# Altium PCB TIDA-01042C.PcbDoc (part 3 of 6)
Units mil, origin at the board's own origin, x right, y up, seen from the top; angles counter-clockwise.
Board outline 8300 x 7100 mil, 8 copper layers (Top Layer, Signal Layer 1, Signal Layer 2, Signal Layer 3, Signal Layer 4, Signal Layer 5, Signal Layer 6, Bottom Layer), stack 59.2 mil thick; 551 components, 303 nets, 1611 pads, 2322 vias.
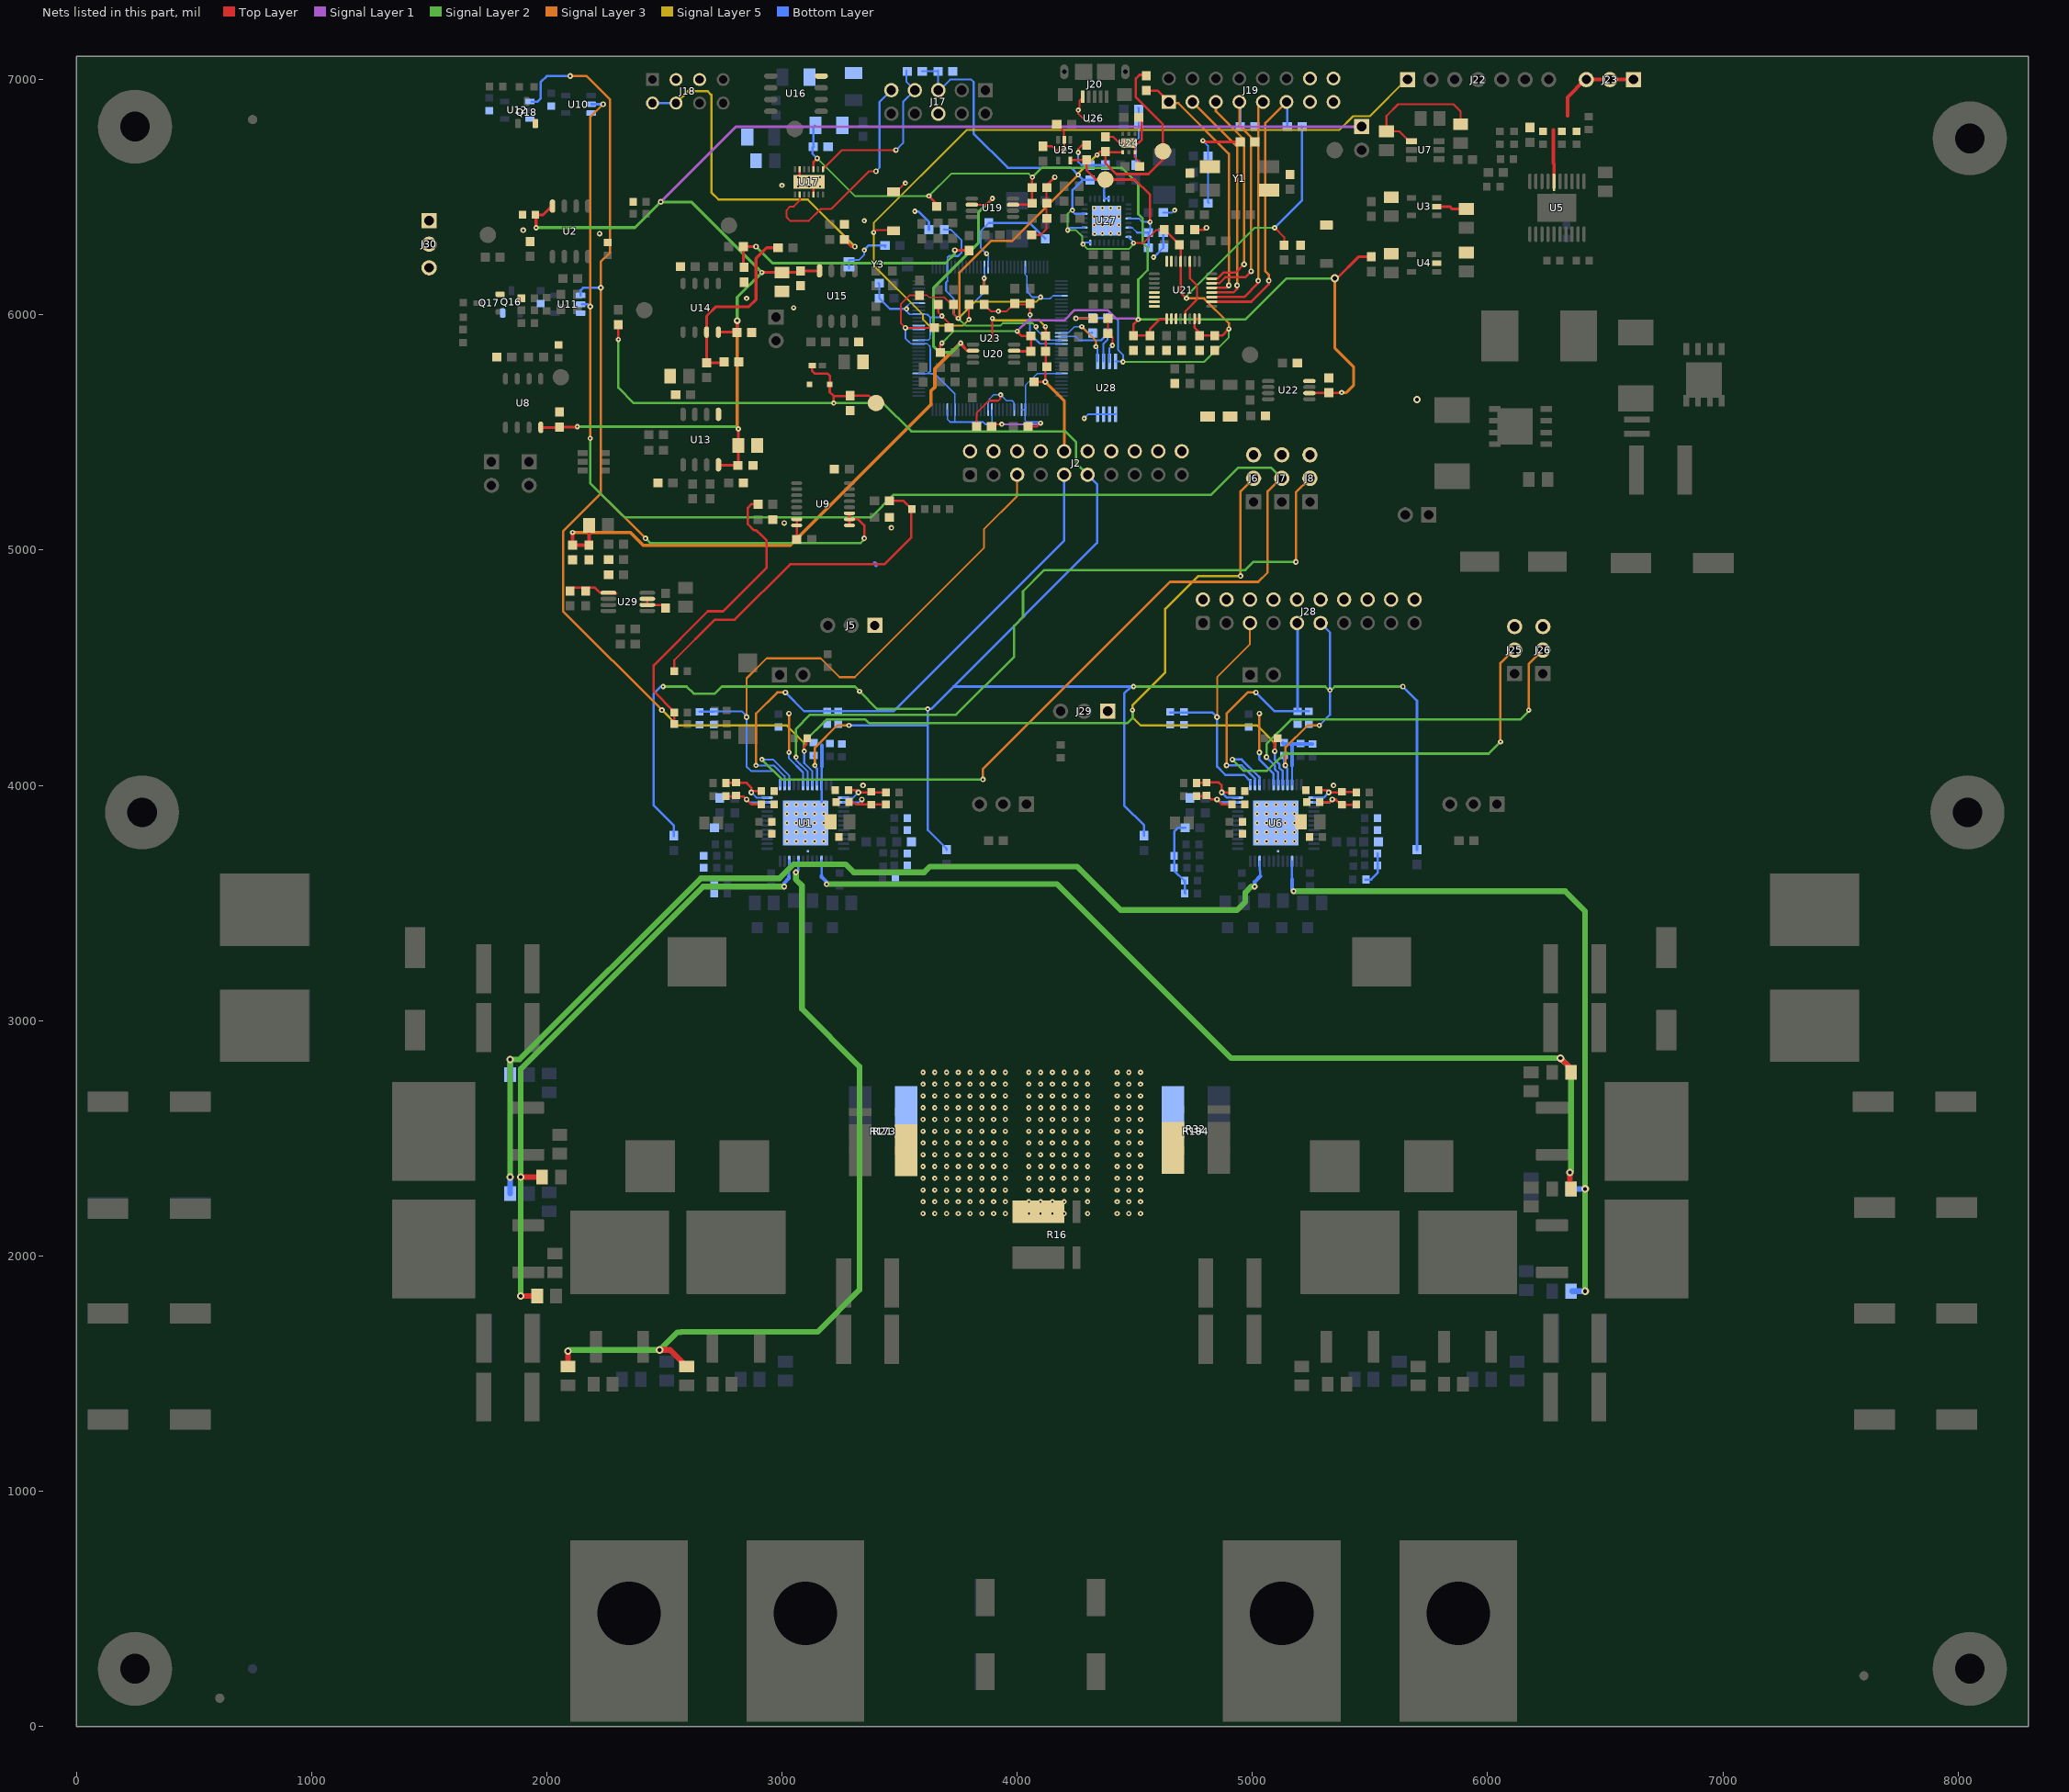
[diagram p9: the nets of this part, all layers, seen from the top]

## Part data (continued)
R113 R115 R128 R130: library part CMP-0022448-4, "RES, 49.9, 1%, 0.1 W, AEC-Q200 Grade 0, 0603", Manufacturer=Vishay-Dale, PartNumber=CRCW060349R9FKEA, Power_W=100mW, Supplier Part Number 1=541-49.9HCT-ND, TempCo="100 ppm/C", Tolerance_%=1%, Value2=0.1W, Value_Code=49R9, ValueDisplayed=49.9
R116 R121 R122 R123 R131: library part CMP-0021990-4, "RES, 100 k, 1%, 0.1 W, AEC-Q200 Grade 0, 0603", Manufacturer=Vishay-Dale, PartNumber=CRCW0603100KFKEA, Power_W=100mW, Supplier Part Number 1=541-100KHCT-ND, TempCo="100 ppm/C", Tolerance_%=1%, Value2=0.1W, Value_Code=100k
R118 R119 R125 R127: library part CMP-0021991-4, "RES, 100, 1%, 0.1 W, AEC-Q200 Grade 0, 0603", Manufacturer=Vishay-Dale, PartNumber=CRCW0603100RFKEA, Power_W=100mW, Supplier Part Number 1=541-100HCT-ND, TempCo="100 ppm/C", Tolerance_%=1%, Value2=0.1W, Value_Code=100R, ValueDisplayed=100
R126 R129: library part CMP-0023081-3, "RES, 3.30 k, 1%, 0.1 W, 0603", Manufacturer="Yageo America", Power_W=100mW, Supplier Part Number 1=311-3.30KHRCT-ND, TempCo="200 ppm/C", Tolerance_%=1%, Value2=0.1W, Value_Code=3k30, ValueDisplayed=3.30k
R134: library part CMP-0022170-4, "RES, 1.00, 1%, 0.1 W, AEC-Q200 Grade 0, 0603", Manufacturer=Vishay-Dale, PartNumber=CRCW06031R00FKEA, Power_W=100mW, Supplier Part Number 1=52K8059, TempCo="100 ppm/C", Tolerance_%=1%, Value2=0.1W, Value_Code=1R00, ValueDisplayed=1.00
R137: library part CMP-0022138-4, "RES, 1.00 M, 1%, 0.1 W, AEC-Q200 Grade 0, 0603", Manufacturer=Vishay-Dale, PartNumber=CRCW06031M00FKEA, Power_W=100mW, Supplier Part Number 1=541-1.00MHCT-ND, TempCo="100 ppm/C", Tolerance_%=1%, Value2=0.1W, Value_Code=1M00, ValueDisplayed=1.00M
R138: library part CMP-0022109-5, "RES, 1.00 k, 1%, 0.1 W, AEC-Q200 Grade 0, 0603", Manufacturer=Vishay-Dale, PartNumber=CRCW06031K00FKEA, Power_W=100mW, Supplier Part Number 1=541-1.00KHCT-ND, TempCo="100 ppm/C", Tolerance_%=1%, Value2=0.1W, Value_Code=1k00, ValueDisplayed=1.00k
R140 R150: "RES, 1.00 M, 1%, 0.1 W, 0603", Manufacturer=Vishay-Dale, Power_W=0.1, Supplier Part Number 1=541-1.00MHCT-ND, TempCo="100 ppm/C", Tolerance_%=1, Value1=1%, Value2=0.1W, Value_Code=1M00, ValueDisplayed=1.00M
R141: "RES, 100, 1%, 0.1 W, 0603", Manufacturer=Vishay-Dale, Power_W=0.1, Supplier Part Number 1=541-100HCT-ND, TempCo="100 ppm/C", Tolerance_%=1, Value1=1%, Value2=0.1W, Value_Code=100R, ValueDisplayed=100
R142: "RES, 0, 5%, 0.1 W, 0603", Manufacturer=Vishay-Dale, Power_W=0.1, Supplier Part Number 1=541-0.0GCT-ND, TempCo="200 ppm/C", Tolerance_%=5, Value1=5%, Value2=0.1W, Value_Code=0000, ValueDisplayed=0
R143: "RES, 4.87 k, 1%, 0.1 W, 0603", Manufacturer=Vishay-Dale, Power_W=0.1, Supplier Part Number 1=541-4.87KHCT-ND, TempCo="100 ppm/C", Tolerance_%=1, Value1=1%, Value2=0.1W, Value_Code=4k87, ValueDisplayed=4.87k
R145: "RES, 2.00 k, 1%, 0.1 W, 0603", Manufacturer=Vishay-Dale, Power_W=0.1, Supplier Part Number 1=541-2.00KHCT-ND, TempCo="100 ppm/C", Tolerance_%=1, Value1=1%, Value2=0.1W, Value_Code=2k00, ValueDisplayed=2.00k
R146: "RES, 51, 5%, 0.1 W, 0603", Manufacturer=Vishay-Dale, Power_W=0.1, Supplier Part Number 1=541-51GCT-ND, TempCo="200 ppm/C", Tolerance_%=5, Value1=5%, Value2=0.1W, Value_Code=51R0, ValueDisplayed=51
R149: "RES, 1.00 k, 1%, 0.1 W, 0603", Manufacturer=Vishay-Dale, Power_W=0.1, Supplier Part Number 1=541-1.00KHCT-ND, TempCo="100 ppm/C", Tolerance_%=1, Value1=1%, Value2=0.1W, Value_Code=1k00, ValueDisplayed=1.00k
R153: "RES, 8.06 k, 1%, 0.1 W, 0603", Manufacturer=Vishay-Dale, Power_W=0.1, Supplier Part Number 1=541-8.06KHCT-ND, TempCo="100 ppm/C", Tolerance_%=1, Value1=1%, Value2=0.1W, Value_Code=8k06, ValueDisplayed=8.06k
R162: library part CMP-0025080-3, "RES, 2.00 k, 0.5%, 0.1 W, 0603", Manufacturer="Yageo America", Power_W=100mW, TempCo="50 ppm/C", Tolerance_%=0.5%, Value2=0.1W, Value_Code=2k00, ValueDisplayed=2.00k
R200: library part CMP-0023560-3, "RES, 4.87 k, 0.1%, 0.1 W, 0603", Manufacturer="Susumu Co Ltd", Power_W=100mW, Supplier Part Number 1=RG16P4.87KBCT-ND, TempCo="25 ppm/C", Tolerance_%=0.1%, Value2=0.1W, Value_Code=4k87, ValueDisplayed=4.87k
R201: "RES, 4.70, 0.5%, 0.1 W, 0603", Manufacturer="Yageo America", Power_W=0.1, TempCo="50 ppm/C", Tolerance_%=0.5, Value1=0.5%, Value2=0.1W, Value_Code=4R70, ValueDisplayed=4.70
S1: library part CMP-0002143-3, "Switch, Tactile, SPST-NO, 0.05A, 12V, SMT", CurrentRating_mA=50A, Manufacturer=E-Switch, PartNumber=TL1015AF160QG, Supplier Part Number 1=EG4344CT-ND
S2: "Switch, Tactile, SPST-NO, 0.05A, 12V, SMT", CurrentRating_mA=50, Manufacturer=E-Switch, Supplier Part Number 1=EG4344CT-ND
S3: "Switch"
T1 T2 T3 T4: "Terminal 70A Lug", Manufacturer=Panduit, Supplier Part Number 1=CXS70-14-C-ND
U1 U6: "Dual Channel 48V-12V Bidirectional Current Controller, PHP0048D", Alternate Manufacturer="Texas Instruments", Alternate PartNumber=LM5170QPHPTQ1
U2: library part LM6142AIM, "17MHz Rail-to-Rail Input and Output Op Amp, D0008A", Alternate Manufacturer="Texas Instruments"
U3 U4: "150-mA, 30-V, 1-uA IQ Voltage Regulators with Enable, DBV0005A", Alternate Manufacturer="Texas Instruments", Alternate PartNumber=TPS70950DBVT
U5: "Wide Voltage Range Buck-Boost Controller, 20-pin TSSOP-EP, Pb-Free", Manufacturer="Texas Instruments", PackageTopMarking=NSUZXYTT*LM5118*MH, PowerWise=Y, Supplier Part Number 1=LM5118MH-ND
U7: library part CMP-0072146-1, "Switched Capacitor Voltage Converter, 6-pin SOT-23", Manufacturer="Texas Instruments", PackageTopMarking=S03A*XTT, PowerWise=N
U8 U14: library part CMP-0041267-2, "Low-Noise, High-Precision, JFET-Input Operational Amplifier, 8 to 36 V, -40 to 125 degC, 8-pin SOIC (D8), Green (RoHS & no Sb/Br)", Manufacturer="Texas Instruments"
U9: library part CMP-0076549-1, "TRIPLE 2-CHANNEL ANALOG MULTIPLEXER/DEMULTIPLEXER, PW0016A (TSSOP-16)", Alternate Manufacturer="Texas Instruments"
U10: "Single Inverter Gate, DBV0005A", Alternate Manufacturer="Texas Instruments"
U11: "Single Power Supply 2-Input Positive NAND Gate CMOS Logic Level Shifter, DBV0005A", Alternate Manufacturer="Texas Instruments"
U12: "Single Power Supply 2-Input Positive OR Gate CMOS Logic Level Shifter, DBV0005A", Alternate Manufacturer="Texas Instruments"
U13: library part CMP-0079943-1, "50-uV Offset, 7-nV/vHz Noise, Low-Power, Precision Instrumentation Amplifier, D0008A (SOIC-8)", Alternate Manufacturer="Texas Instruments", Alternate PartNumber=INA828IDR
U15: library part CMP-0079847-1, "36-V Precision, Rail-to-Rail Output, Operational Amplifier, D0008A (SOIC-8)", Alternate Manufacturer="Texas Instruments"
U16: library part CMP-0032617-1, "Low Noise, Very Low Drift, Precision Voltage Reference, -40 to 125 degC, 8-pin SOIC (D), Green (RoHS & no Sb/Br)", Manufacturer="Texas Instruments", PartNumber=REF5050AID, Rating=Catalog, Temp Coeff(Max)(ppm/ degree C)=3
U17: library part CMP-0013342-2, "QUAD 16-BIT, 1LSB INL, BUFFERED, VOLTAGE-OUTPUT DIGITAL-to-ANALOG CONVERTERS, DMD0014A (VSON-14)", Alternate Manufacturer="Texas Instruments", PartNumber=DAC80004IDMD
U19 U20: library part CMP-0074888-1, "Low-Power, High Supply Range, 60-MHz, Fully Differential Amplifier, DGK0008A (VSSOP-8)", Alternate Manufacturer="Texas Instruments", Alternate PartNumber=THS4561IDGKT
U21: library part CMP-0075938-2, "24-Bit, 128kSPS, 4-Ch, Simultaneous Sampling, Delta-Sigma ADC, PBS0032A (TQFP-32)", Alternate Manufacturer="Texas Instruments", Alternate PartNumber=ADS131A04IPBS
U22: library part CMP-0032584-1, "Low Noise, Very Low Drift, Precision Voltage Reference, -40 to 125 degC, 8-pin MSOP(DGK), Green (RoHS & no Sb/Br)", Manufacturer="Texas Instruments", PartNumber=REF5025IDGKR, Rating=Military, Temp Coeff(Max)(ppm/ degree C)=3
U23: library part CMP-0029864-2, "Tiva C Series Microcontroller, 1024 KB Flash, 256 KB SRAM, 12 Bit, 20 Channels, -40 to 85 degC, 128-Pin TQFP (PDT), Green (RoHS & no Sb/Br), Tape and Reel", Manufacturer="Texas Instruments", Temperature Range="-40 to 85 degC"
U24: "1-A Low-Dropout Regulator With Reverse Current Protection, DRV0006A", Alternate Manufacturer="Texas Instruments", Alternate PartNumber=TPS73733DRVT
U25: "Single Output High PSRR LDO, 150 mA, Fixed 1.8 V Output, 2.5 to 6.5 V Input, with Low IQ, 5-pin SC70 (DCK), -40 to 85 degC, Green (RoHS & no Sb/Br)", Alternate Manufacturer="Texas Instruments", Alternate PartNumber=Equivalent, Supplier Part Number 1=296-19646-2-ND
U26: library part CMP-0043122-2, "USB ESD Solution with Power Clamp, 4 Channels, -40 to +85 degC, 6-pin SON (DRY), Green (RoHS & no Sb/Br)", Breakdown Voltage(Min)(V)=6, IO Capacitance(Typ)(pF)=0.8, IO Leakage Current(nA)=10, Manufacturer="Texas Instruments"
U27: "Highly Integrated Full Featured Hi-Speed USB 2.0 ULPI Transceiver, QFN-32", Manufacturer=Microchip, Supplier Part Number 1=USB3320C-EZK-ND
U28: "256K I2C™ CMOS Serial EEPROM, TSSOP-8", Manufacturer=Microchip, Supplier Part Number 1=24AA256-I/ST-ND
U29: "Low Noise Negative Bias Generator, 8-pin Mini SOIC, Pb-Free", Manufacturer="Texas Instruments", PackageTopMarking=ZXTT*F26A, PowerWise=N, Supplier Part Number 1=LM7705MM-ND
Y1: library part CMP-0004606-3, "Crystal, 16.384 MHz, 20 pF, SMD", Frequency_Fixed=16.384MHz, Frequency Stability=+/-50ppm, Manufacturer="CTS Electrocomponents", PartNumber=407F35E016M3840, Supplier Part Number 1=CTX682CT-ND
Y2: "Crystal, 25 MHz, 18 pF, SMD", Frequency="25 MHz", Frequency Stability=±30ppm, Manufacturer="Abracon Corportation", Supplier Part Number 1=535-10645-1-ND
Y3: "CRYSTAL, 32.768KHZ, 7PF, SMD", Frequency=32.768KHZ, Frequency Stability=±20ppm, Manufacturer="Seiko Instruments", Supplier Part Number 1=728-1065-1-ND
Y4: "Crystal, 24 MHz, 18 pF, SMD", Frequency="24 MHz", Frequency Stability=±30ppm, Manufacturer="Abracon Corportation", Supplier Part Number 1=535-10643-1-ND
ZZ1: library part AssemblyNoteLabel, Alternate Manufacturer=-
ZZ2 ZZ3 ZZ4: library part AssemblyNote, Alternate Manufacturer=-

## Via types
v1: diameter 32, hole 16, Top Layer to Bottom Layer, tented both sides, 1077 vias
v2: diameter 22, hole 8, Top Layer to Bottom Layer, tented both sides, 583 vias
v3: diameter 32, hole 16, Top Layer to Bottom Layer, 233 vias
v4: diameter 24, hole 10, Top Layer to Bottom Layer, tented both sides, 153 vias
v5: diameter 24, hole 8, Top Layer to Bottom Layer, 96 vias
v6: diameter 19.68, hole 7.87, Top Layer to Bottom Layer, 70 vias
v7: diameter 24, hole 10, Top Layer to Bottom Layer, 44 vias
v8: diameter 28, hole 8, Top Layer to Bottom Layer, tented top, 24 vias
v9: diameter 22, hole 8, Top Layer to Bottom Layer, 18 vias
v10: diameter 19.68, hole 8, Top Layer to Bottom Layer, 16 vias
v11: diameter 50, hole 28, Top Layer to Bottom Layer, 3 vias
v12: diameter 36, hole 20, Top Layer to Bottom Layer, 2 vias
v13: diameter 26, hole 12, Top Layer to Bottom Layer, 1 vias
v14: diameter 28, hole 12, Top Layer to Bottom Layer, tented both sides, 1 vias
v15: diameter 24, hole 10, Top Layer to Bottom Layer, tented top, 1 vias

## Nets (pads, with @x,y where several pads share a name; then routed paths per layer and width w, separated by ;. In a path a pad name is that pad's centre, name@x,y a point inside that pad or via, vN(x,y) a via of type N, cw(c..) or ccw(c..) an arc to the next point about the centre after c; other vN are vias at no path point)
1.8V: C177.2 C178.2 C183.1 U25.5 U27.28 U27.30 V1.8.1 | length 842.3
  Top Layer w10: U25.5@4225,6660 4226.5,6658.5 C183.1@4295,6658.5 4295,6615 4335,6575 V1.8.1@4375,6575 4500,6575 4565,6510 v2(4565,6395)
  Bottom Layer w6: U27.30@4475,6370 4490,6370 4510,6350 4511.24,6350
  Bottom Layer w8: U27.28@4473.31,6409.84 4517.51,6409.84 4532.35,6395 v2@4560,6395 ; C177.2@4560,6350 4565,6355 v2(4565,6395)
  Bottom Layer w10: 4511.24,6350 C177.2@4558.5,6350 ; C178.2@4555,6285 4558.5,6288.5 C177.2@4558.5,6350 ; C177.2@4560,6350 C177.2@4558.5,6350
-0.2V: C228.1 C229.1 L8.1 U19.6 U20.6 | length 3366.9
  Top Layer w9: U19.6@3807.4,6467.8 3867.8,6467.8 v2(3895,6495)
  Top Layer w12: v2(3760,5880) 3771.95,5868.05 3771.95,5863.97 ; 3770,5865 3787.2,5847.8 U20.6@3812.4,5847.8 U20.6@3809.54,5850.65
  Top Layer w15: C229.1@2105,5025 2108.5,5021.5 C229.1@2110,5021.5 ; v2(2110,5075) C229.1@2110,5021.5 ; C228.1@2180,5021.5 C229.1@2110,5021.5 ; C228.1@2180,5025 L8.1@2180,5105
  Signal Layer 2 w12: v2(3760,5880) 3720,5840 3670,5840 3645,5865 3645,6115 3835,6305 3835,6435 v2(3895,6495)
  Signal Layer 3 w15: v2(2110,5075) 2356.29,5075 2411.29,5020 3035,5020 3633.63,5618.63 3633.63,5676.37 3650,5692.75 3650,5770 v2(3760,5880)
-5V: C97.1 C108.1 C109.1 C112.1 C119.1 C120.1 C189.1 J16.1 U2.4 U8.4 U13.4 U14.4 U15.4 | length 6559.2
  Top Layer w12: v2(1955,6370) 1955,6425 1985,6425 U2.4@2025,6465 ; U8.4@1975,5521.65 2053.35,5521.65 C97.1@2055,5520 ; C97.1@2055,5523.5 v9@2131.5,5523.5 ; U13.4@2730,5362.72 2732.72,5360 C108.1@2813.5,5360 2815,5360 v9(2815,5515) ; U14.4@2730,5926.65 2803.35,5926.65 C112.1@2805,5925 ; C112.1@2808.5,5925 v14@2808.5,5973.5 ; v2(2915,6180) C120.1@3000,6180 3080,6180 3087.28,6187.28 U15.4@3160,6187.28
  Signal Layer 1 w12: v4(2485,6480) 2805,6800 J16.1@5465,6800
  Signal Layer 2 w12: v2(1955,6370) 1955.87,6370.87 2375.87,6370.87 v4(2485,6480) 2615,6480 v2(2915,6180) 2810,6075 v14(2810,5975) ; v9(2130,5525) 2805,5525 v9(2815,5515)
  Signal Layer 3 w12: v14(2810,5975) 2810,5515 v9@2815,5510
ADC_SPI_CS: J19.5 U21.23 | length 902.8
  Top Layer w10: U21.23@4827.05,6154.21 4827.95,6155.12 4852.54,6155.12 4877.42,6180 4930,6180 v7(4965,6215)
  Signal Layer 3 w10: J19.5@4845,6905 4845,6865 4965,6745 v7(4965,6215)
ADC_SPI_DONE: J19.11 R123.1 U21.18 | length 1198.6
  Top Layer w10: U21.18@4827.05,6055.79 4995.79,6055.79 5070,6130 v7(5070,6145)
  Signal Layer 3 w10: v7(5070,6145) 5070,6170 5055,6185 5055,6815 J19.11@5145,6905
  Bottom Layer w10: J19.11@5145,6905 5148.5,6901.5 R123.1@5148.5,6800
ADC_SPI_DRDY: J19.9 U21.19 | length 1000.9
  Top Layer w10: U21.19@4827.05,6075.47 4965.47,6075.47 5025,6135 v7(5025,6145)
  Signal Layer 3 w10: v7(5025,6145) 5025,6165 5025,6885 J19.9@5045,6905
ADC_SPI_MISO: J19.1 R122.1 U21.21 | length 1098.4
  Top Layer w10: R122.1@4550,6953.5 4596.5,6953.5 J19.1@4645,6905 J19.1@4646.5,6903.5 ; U21.21@4827.05,6114.84 4889.84,6114.84 v7(4900,6125)
  Signal Layer 3 w10: J19.1@4645,6900 4685,6900 4900,6685 v7(4900,6125)
ADC_SPI_MOSI: J19.3 U21.20 | length 987.8
  Top Layer w10: U21.20@4827.05,6095.16 4920.16,6095.16 4935,6110 v7(4935,6125)
  Signal Layer 3 w10: J19.3@4745,6905 4935,6715 v7(4935,6125)
ADC_SPI_SCLK: J19.7 R138.2 U21.22 | length 1043.1
  Top Layer w10: U21.22@4827.05,6134.53 4859.53,6134.53 4885,6160 4970,6160 v7(4995,6185)
  Signal Layer 3 w10: J19.7@4945,6910 J19.7@4945,6905 4945,6805 4995,6755 v7(4995,6185)
  Bottom Layer w10: J19.7@4940,6905 4948.5,6896.5 R138.2@4948.5,6800
AGND: C1.2 C2.1 C3.1 C5.2 C6.2 C8.2 C9.1 C11.2 C13.2 C14.2 C16.2 C17.2 C19.1 C31.2 C33.2 C34.2 C35.2 C36.2 C37.2 C44.2 C45.2 C72.2 C73.2 C74.2 C75.2 C76.2 C78.2 C82.2 C83.2 C84.2 C90.2 C91.1 C93.2 C94.1 C96.2 C97.2 C98.2 C99.1 C100.2 C104.2 C105.2 C106.2 C107.2 C108.2 C109.2 C110.2 C111.2 C112.2 C113.1 C116.2 C117.2 C118.1 C119.2 C120.2 C121.1 C122.2 C123.2 C124.2 C125.2 C126.2 C127.2 C128.2 C131.2 C132.2 C133.2 C134.2 C135.2 C136.2 C137.2 C138.2 C139.2 C140.2 C141.2 C145.1 C146.1 C149.1 C152.2 C153.2 C155.2 C156.2 C157.2 C158.2 C159.2 C160.2 C161.2 C189.2 C190.2 C191.2 C194.2 C196.2 C197.2 C199.2 C200.2 C202.2 C203.2 C204.2 C205.2 C218.2 C223.2 C224.2 C225.2 C226.2 C227.2 C228.2 C229.2 D5.2 J2.2 J2.4 J2.6 J2.8 J2.10 J2.12 J2.14 J2.16 J2.18 J2.20 J5.1 J6.3 J7.3 J8.3 J17.6 J18.3 J18.5 J19.13 J19.14 J19.15 J19.16 J23.1 J23.2 J23.3 J25.3 J26.3 J28.2 J28.4 J28.6 J28.8 J28.10 J28.12 J28.14 J28.16 J28.18 J28.20 J29.1 J30.1 J30.2 J30.3 NT1.1 NT2.1 NT3.1 Q16.2 Q17.2 Q18.2 R2.2 R3.2 R6.1 R7.2 R9.2 R11.1 R13.1 R15.1 R17.1 R18.1 R19.1 R20.1 R23.2 R46.1 R49.1 R67.1 R78.1 R86.2 R87.1 R89.2 R92.1 R112.1 R126.1 R138.1 R147.2 R148.1 R156.1 R158.1 R167.1 R169.1 R170.1 R171.1 R172.1 S1.2 U1.42 U1.46 U1.49 U3.2 U4.2 U5.6 U6.42 U6.46 U6.49 U7.1 U9.7 U9.8 U10.3 U11.3 U12.3 U13.5 U16.4 U17.6 U17.12 U17.15 U21.5 U21.6 U21.7 U21.8 U21.10 U21.11 U21.13 U21.27 U21.31 U21.32 U22.4 U29.2 U29.3 U29.5 Y1.2 Y1.4 | length 5161.6
  Top Layer w8: 3895,5895 v2(3895,5985)
  Top Layer w9: R112.1@4061.5,6340 4100,6340 4125,6365 C134.2@4125,6540 ; C132.2@4120,5770 C132.2@4130,5780 ; v2(4120,5950) 4121.5,5948.5 C136.2@4121.5,5910 C135.2@4121.5,5845 ; C132.2@4121.5,5788.5 C132.2@4125,5785 ; C134.2@4126.5,6540 4126.5,6551.5 v4(4160,6585) ; U21.13@4715,5985 4715,6015 4765,6065 4765,6125 4734.53,6155.47 U21.27@4734.53,6227.05 ; U21.27@4733.12,6228.12 U21.27@4735,6230 ; C156.2@4755,6361.5 4796.5,6361.5 v4(4805,6370) ; U7.1@5676.93,6737.4 5667.6,6737.4 5625,6780 C78.2@5570,6780 5570,6845 5620,6895 5855,6895 5885,6865 C76.2@5885,6810
  Top Layer w9.8: C225.2@2095,4840 2205,4840 2226.61,4818.39 U29.5@2262.32,4818.39 2266.28,4814.43 2295.89,4814.43 ; U29.2@2427.68,4767.2 2487.8,4767.2 C223.2@2510,4745 ; U29.2@2427.68,4767.68 U29.3@2427.68,4792.8 ; U9.7@3062.8,5131.02 U9.8@3062.8,5105.43 3062.8,5042.2 R67.1@3065,5040
  Top Layer w10: U17.15@3065,6585 3075.63,6595.63 U17.6@3075.63,6619.13 ; U17.12@3134.69,6510.87 3134.69,6544.68 U17.15@3135,6545 ; R126.1@4071.5,5715 v4(4120,5715) C132.2@4120,5770 ; C132.2@4121.5,5788.5 C135.2@4121.5,5845
  Top Layer w13: U3.2@5777.24,6460 U3.2@5784.13,6460 5840,6460 5850,6450 C34.2@5910,6450 ; 6280,6645 6282.2,6642.8 U5.6@6282.2,6567.2
  Top Layer w15: 6340,6845 6340,6925 6415,7000 J23.3@6420,7000 J23.2@6520,7000 J23.1@6620,7000
  Top Layer w16: v6(3178.74,3840) C6.2@3214.57,3840 ; 6280,6645 6280,6785
  Signal Layer 3 w10: v2(3030,4140) v4(3030,4305) ; v4(5030,4140) v4(5030,4305)
  Signal Layer 3 w12: v4(4120,5715) 4200,5635 J2.10@4200,5420 J2.10@4200,5400
  Signal Layer 5 w9: v2(3895,5985) 3903.37,5976.63 4093.37,5976.63 v2(4120,5950)
  Bottom Layer w8: v2@3030,4137.7 3030,4115 3090.16,4054.84 U1.42@3090.16,3998.46
  Bottom Layer w9: U6.46@5168.9,4002.4 5168.9,4083.9
  Bottom Layer w9.8: U1.49@3168.9,3928.58 3168.9,3998.46 3168.9,4080 ; R170.1@4710,3595 4667.44,3637.56 C19.1@4667.44,3700 4667.44,3802.44 4685,3820 R167.1@4713.5,3820 R167.1@4715,3820 ; R170.1@4712.44,3595 4712.44,3542.56 C203.2@4715,3540 ; v4(5030,4140) 5030,4110 5079.68,4060.32 5079.68,4060.01 5090.16,4049.53 U6.42@5090.16,4002.4 ; C197.2@5480,3600 C197.2@5482.56,3600 5505.12,3600 5532.56,3627.44 R172.1@5532.56,3710
  Bottom Layer w16: 3170,4080 3170,4088.9 ; 3170,4092.8 3170,4170 ; 3395,4945 3400,4940 3400,4935 ; C196.2@5130,4180 5134.11,4175.89 5168.9,4175.89 ; 5168.9,4083.9 5168.9,4175.89 ; 5168.9,4178.9 5168.9,4175.89 ; R148.1@5255,4175.89 5168.9,4175.89
  other v1: 5700,5640
  other v4: 3345,4000 5345,4000 3465,5095 3010,5115 2225,6345 1900,6360
  other v6: 3021.26,3761.26 3060.63,3761.26 3100,3761.26 3139.37,3761.26 3178.74,3761.26 5021.26,3761.26 5060.63,3761.26 5100,3761.26 5139.37,3761.26 5178.74,3761.26 3021.26,3800.63 3060.63,3800.63 3100,3800.63 3139.37,3800.63 3178.74,3800.63 5021.26,3800.63 5060.63,3800.63 5100,3800.63 5139.37,3800.63 5178.74,3800.63 3021.26,3840 3060.63,3840 3100,3840 3139.37,3840 5021.26,3840 5060.63,3840 5100,3840 5139.37,3840 5178.74,3840 3021.26,3879.37 3060.63,3879.37 3100,3879.37 3139.37,3879.37 3178.74,3879.37 5021.26,3879.37 5060.63,3879.37 5100,3879.37 5139.37,3879.37 5178.74,3879.37 3021.26,3918.74 3060.63,3918.74 3100,3918.74 3139.37,3918.74 3178.74,3918.74 5021.26,3918.74 5060.63,3918.74 5100,3918.74 5139.37,3918.74 5178.74,3918.74 3067.76,6545.32 3115,6545.32 3162.24,6545.32 3067.76,6584.68 3115,6584.68 3162.24,6584.68
  other v9: 3050,6030 2850,6070 3350,6400 3000,6550
AVDD: C126.1 C127.1 C133.1 C134.1 C135.1 C136.1 C137.1 C138.1 C160.1 R116.2 R131.2 R165.2 U17.3 U19.3 U20.3 U21.9 U22.2 | length 5801.1
  Top Layer w10: U17.3@3134.69,6619.13 3134.69,6649.68 v7(3150,6665) ; v2(3625,6505) 3658.5,6471.5 R116.2@3658.5,6460 ; R131.2@3673.5,5840 3673.5,5873.5 v2(3680,5880) ; U19.3@3982.6,6467.8 4057.8,6467.8 C133.1@4065,6475 ; U20.3@3985,5845 C135.1@4058.5,5845 ; v2(4000,5930) 4020,5910 C136.1@4058.5,5910 4058.5,5846.5 C135.1@4060,5845 ; v2@4063.5,6583.5 C134.1@4063.5,6540 4063.5,6481.5 C133.1@4065,6480 ; C138.1@4495,5910 4496.5,5911.5 C137.1@4565,5911.5 4565,5940 4605,5980 U21.9@4635,5980 ; C138.1@4495,5911.5 4495,5960 v9(4515,5980) ; U22.2@5240,5670 5241.5,5668.5 C160.1@5325,5668.5 5378.5,5668.5 v2(5380,5670)
  Top Layer w12: v12(5350,6155) 5360,6155 5451.5,6246.5 R165.2@5505,6246.5
  Signal Layer 1 w10: v2(4000,5930) 4046.13,5976.13 4200,5976.13 4243.87,6020 4264.82,6020 4295.18,6020 4385,6020 4420,5985 ; 4420,5983.87 4511.13,5983.87 v9(4515,5980)
  Signal Layer 2 w8: v7(3150,6665) 3310,6505 v2(3625,6505) 3720,6600 4050,6600 v2(4065,6585) ; v2@3675,5880 v2(3680,5880) 3730,5930 v2(4000,5930)
  Signal Layer 2 w10: v2(4065,6585) 4105,6625 4445,6625 4515,6555 4515,6427.75 4533.87,6408.87 4533.87,6305 ; 4535,6305 4555,6285 4555,6190 4515,6150 v9(4515,5980) 4970,5980 5145,6155 v12(5350,6155)
  Signal Layer 3 w12: v12(5350,6155) 5350,5860 5430,5780 5430,5700 5400,5670 v2(5380,5670)
  Bottom Layer w10: C127.1@3133.5,6715 3133.5,6798.5 C126.1@3140,6805 ; C127.1@3135,6715 3130,6710 3130,6685 v7(3150,6665)
CLRn: J17.9 U17.9 | length 972.8
  Top Layer w8: U17.9@3075.63,6510.87 3075.63,6485.63 3050,6460 3035,6460 3020,6445 3020,6415 3035,6400 3115,6400 3165,6450 3210,6450 3370,6610 v7(3400,6610)
  Bottom Layer w8: v7(3400,6610) 3415,6625 3415,6905 J17.9@3465,6955
CS1A: C72.1 C80.1 R56.1 U1.36 | length 267.6
  Top Layer w9.8: R56.1@2753.62,4000 R56.1@2758.62,4000 ; R56.1@2762.56,4010 2850,4010 2870,3990 v4(2870,3970) ; v4@2875,3975 C72.1@2912.44,3975 C72.1@2921.38,3975
  Bottom Layer w8: v4(2870,3970) 2891.73,3948.27 U1.36@2941.54,3948.27
CS1B: C73.1 C80.2 R57.1 U1.35 | length 268.7
  Top Layer w9.8: R57.1@2762.33,3952.33 2837.67,3952.33 v4(2850,3940) 2870,3920 C73.1@2921.38,3920
  Bottom Layer w8: v4(2850,3940) 2861.42,3928.58 U1.35@2941.54,3928.58
CS2A: C75.1 C81.2 R58.1 U1.1 | length 246.1
  Top Layer w9.8: C75.1@3278.62,3980 C75.1@3282.56,3980 3315,3980 v4(3325,3970) R58.1@3442.44,3970 R58.1@3445,3970
  Bottom Layer w8: U1.1@3258.46,3948.27 3303.27,3948.27 v4(3325,3970)
CS2B: C74.1 C81.1 R59.1 U1.2 | length 271.6
  Top Layer w9.8: C74.1@3285,3925 3310,3925 3315,3920 3340,3920 ; v4(3340,3940) 3340,3920 ; R59.1@3440,3920 3340,3920
  Signal Layer 3 w9.8: v4(3340,3940) v4@3345.31,3940
  Bottom Layer w8: U1.2@3258.46,3928.58 3328.58,3928.58 3335,3935 v4@3345,3935
CS3A: C95.1 C190.1 R177.1 U6.36 | length 264.2
  Top Layer w9.8: R177.1@4762.56,4010 C95.1@4805,4010 ; C95.1@4805,4012.56 4857.44,4012.56 4870,4000 v4(4870,3970) C190.1@4915,3970
  Bottom Layer w9.8: v4(4870,3970) 4891.73,3948.27 U6.36@4937.6,3948.27
CS3B: C95.2 C191.1 R178.1 U6.35 | length 268.4
  Top Layer w10: R178.1@4762.56,3955 C95.2@4805,3955 ; C95.2@4805,3960 4825,3940 v4(4850,3940) 4870,3920 C191.1@4912.44,3920 C191.1@4915,3920
  Bottom Layer w9.8: v4@4845,3945 v4(4850,3940) 4861.42,3928.58 U6.35@4937.6,3928.58
CS4A: C198.2 C200.1 R186.1 U6.1 | length 238.9
  Top Layer w10: C200.1@5280,3975 5285,3980 5315,3980 v4(5325,3970) C198.2@5380,3970 ; C198.2@5380,3972.56 5437.44,3972.56 R186.1@5440,3970
  Bottom Layer w10: U6.1@5262.4,3948.27 5303.27,3948.27 v4(5325,3970)
CS4B: C198.1 C199.1 R187.1 U6.2 | length 257.4
  Top Layer w10: C199.1@5286.02,3928.58 5328.58,3928.58 v4(5340,3940) 5355,3940 C198.1@5380,3915 ; C198.1@5380,3917.44 5442.44,3917.44 R187.1@5445,3920
  Bottom Layer w10: U6.2@5262.4,3928.58 5328.58,3928.58 v4(5340,3940)
DGND: C162.2 C163.1 C164.2 C165.1 C166.1 C167.1 C168.1 C169.1 C170.1 C171.1 C172.2 C173.2 C174.1 C175.2 C176.1 C177.1 C178.1 C179.2 C180.2 C181.2 C182.2 C183.2 C184.2 C185.1 C186.1 C187.1 C188.2 J20.5 R143.2 R147.1 R153.1 R154.1 S2.1 U23.10 U23.17 U23.48 U23.55 U23.58 U23.80 U23.114 U24.3 U24.7@4475,6730 U25.2 U26.4 U27.33 U28.1 U28.2 U28.3 U28.4 U28.7 Y3.2 Y3.3 | length 4664.5
  Top Layer w6: C179.2@4515,6835 4530,6820
  Top Layer w8: S2.1@3475,6522.68 3487.68,6522.68 v2(3525,6560) ; C169.1@3665,6040 3665,6010 v2(3680,5995) 3711.5,5963.5 C168.1@3711.5,5945 ; C165.1@3828.5,5525 3828.5,5583.5 3880,5635 3920,5635 3930,5645 v2(3930,5660) ; C167.1@3860,6043.5 3888.5,6015 v2(3920,6015) 3955,6015 C172.2@3983.5,6043.5 ; C172.2@3990,6050 C172.2@3983.5,6043.5 ; v2(4055,6000) C173.2@4055,6045 ; C173.2@4055,6048.5 C173.2@4055,6045 ; C184.2@4110,6716.5 4148.5,6716.5 4165,6700 v2(4200,6700) U25.2@4200,6744.29 4200,6745 4198.5,6746.5 4198.5,6780 C182.2@4168.5,6810 ; v2(4260,6690) 4260,6705 4276.5,6721.5 C183.2@4295,6721.5 ; J20.5@4280,6925 4265,6910 4265,6875 v2(4260,6870) 4260,6855 4290,6825 U26.4@4305,6825 ; C166.1@4375,6000 4375,5985 C166.1@4386.5,5985 C174.1@4386.5,5923.5 ; C180.2@4375,6756.5 4408.5,6756.5 4435,6730 U24.7@4450,6730 ; C174.1@4385,5925 C174.1@4386.5,5923.5 ; v2(4405,5870) 4405,5905 C174.1@4386.5,5923.5 ; U24.3@4500,6695 4500,6670 4521.5,6648.5 C181.2@4521.5,6630 ; U24.3@4500.59,6691.61 U24.7@4500.59,6724.41 ; C172.2@3983.5,6043.5 4053.5,6043.5 C173.2@4055,6045
  Top Layer w10: U24.7@4495,6730 v6(4496.65,6730) 4515,6730 4530,6745 4530,6820 4530,6826.5 C179.2@4516.5,6840 ; v2(4790,6740) 4795,6735 R147.1@4948.5,6735
  Bottom Layer w6: v9@3530,6035 3544.61,6049.61 U23.58@3581.85,6049.61 ; 3540,6005 3542.64,6002.36 U23.55@3581.85,6002.36 3617.64,6002.36 3620,6000 ; U23.48@3581.85,5892.13 3622.13,5892.13 3630,5900 3630,5915 ; v2(3870,6260) 3877.13,6252.87 U23.80@3877.13,6203.15 ; U23.17@3877.13,5596.85 3878.06,5597.79 3878.06,5631.22 3882.13,5635.28 3882.13,5642.13 3900,5660 v2(3930,5660) 3954.72,5635.28 3978.78,5635.28 3986.43,5627.64 3986.43,5597.79 U23.10@3987.36,5596.85 ; 4095,5880 4098.62,5876.38 U23.114@4188.15,5876.38
  Bottom Layer w8: Y3.2@3285.98,6197.28 Y3.3@3285.98,6232.72 3327.72,6232.72 3350,6255 v2(3350,6275) ; C170.1@3410,6135 3413.5,6131.5 R143.2@3413.5,6070 ; v9@3530,6035 v9(3530,6025) 3530,6015 3540,6005 ; 3620,6000 3630,5990 ; 3630,5915 3630,5990 ; v2(3680,5995) 3675,5990 3630,5990 ; v2(3870,6260) 3845,6285 3845,6355 C162.2@3880,6390 ; v2(4055,6000) 4055,5920 4095,5880 ; v2(4260,6690) 4260,6650 4273.5,6636.5 C176.1@4310,6636.5 4373.5,6636.5 C175.2@4375,6635 ; v2(4285,5560) 4302.8,5577.8 U28.4@4341.61,5577.8 U28.3@4367.2,5577.8 U28.2@4392.8,5577.8 4417.8,5577.8 U28.1@4420,5580 ; U28.7@4390.3,5799.7 U28.7@4392.8,5797.2 ; U28.7@4392.8,5802.2 4392.8,5857.8 v2(4405,5870) ; v6@4495.83,6729.17 4505,6720 R153.1@4505,6636.5 ; v6@4495.83,6730.83 4516.5,6751.5 C187.1@4516.5,6810 4516.5,6878.5 C188.2@4515,6880 ; v2@4581.5,6245 C178.1@4621.5,6285 C177.1@4621.5,6350 ; R154.1@4621.5,6435 4660,6435 v2(4670,6445) ; v2(4790,6740) 4811.5,6718.5 C186.1@4811.5,6675 4811.5,6478.5 C185.1@4815,6475
  Bottom Layer w10: v2(3350,6275) 3370,6295 C171.1@3438.5,6295 ; R143.2@3415,6070 3460,6025 v9(3530,6025) ; C171.1@3438.5,6290 3438.5,6293.5 C171.1@3440,6295 ; v2(3565,6440) 3580,6440 3625,6395 C163.1@3625,6361.5 ; C162.2@3880,6390 4053.5,6390 C164.2@4120,6323.5
  other v2: 4580,6245
  other v6: 4453.35,6730
  other v10: 4330,6345 4362.28,6346.85 4397.72,6346.85 4433.15,6346.85 4326.85,6382.28 4362.28,6382.28 4397.72,6382.28 4433.15,6382.28 4326.85,6417.72 4362.28,6417.72 4397.72,6417.72 4433.15,6417.72 4326.85,6453.15 4362.28,6453.15 4397.72,6453.15 4433.15,6453.15
DIR: J6.2 R102.2 R144.2 U1.44 U6.44 U9.9 U9.10 U9.11 U11.1 U12.1 | length 9504.4
  Top Layer w10: v2(3095,4145) 3095,4165 3105,4175 R102.2@3105,4200 ; U9.11@3287.2,5156.61 3287.2,5132.8 U9.10@3288.98,5131.02 ; U9.9@3290,5105 3287.2,5107.8 U9.10@3287.2,5131.02 U9.10@3288.98,5131.02 ; v4(3350,5050) 3350,5105 3323.98,5131.02 U9.10@3288.98,5131.02
  Top Layer w12: v4(5095,4145) 5095,4190 R144.2@5105,4200
  Signal Layer 2 w10: v4(2420,5050) 2440,5030 3335,5030 v4@3350,5045 ; v2(3095,4145) 3095,4185 3190,4280 3355,4280 3370,4265 4470,4265 4490,4285 v2(4490,4320)
  Signal Layer 3 w10: v4(2100,7015) 2170,7015 2270,6915 2270,6265 2230,6225 v4(2230,6115) 2230,5240 ; v4(2420,5050) 2230,5240 ; v4(2490,4320) 2070,4740 2070,5080 2230,5240 ; v4(4950,4890) 4950,5250 J6.2@5005,5305
  Signal Layer 5 w10: v4(2490,4320) 2555,4255 3020,4255 3095,4180 v2(3095,4145) ; v4(4950,4890) 4770,4890 4630,4750 4630,4480 4490,4340 v2(4490,4320) 4490,4290 4525,4255 5020,4255 5095,4180 v4(5095,4145)
  Bottom Layer w8: v2(3095,4145) 3095,4094.9 3129.53,4060.37 U1.44@3129.53,3998.46
  Bottom Layer w10: U12.1@1935,6905 1960,6905 1975,6920 1975,6990 2000,7015 v4(2100,7015) ; U11.1@2144.13,6082.4 2145,6083.27 2145,6105 2155,6115 v4(2230,6115) v4@2235,6115 ; v4(5095,4145) 5095,4110.14 5112.77,4092.36 5112.77,4092.23 5115.13,4089.87 5115.13,4074.7 5129.53,4060.3 U6.44@5129.53,4002.4
DVDD_3.3V: C128.1 C139.1 C140.1 C141.1 C165.2 C166.2 C167.2 C168.2 C175.1 C176.2 C180.1 DVDD_3V3.1 J17.5 R99.1 R120.2 R121.2 R122.2 R123.2 R139.2 R140.2 R142.1 R146.1 R151.2 R152.2 U21.15 U21.16 U21.29 U23.7 U23.8 U23.16 U23.26 U23.28 U23.39 U23.47 U23.51 U23.52 U23.69 U23.79 U23.90 U23.101 U23.113 U23.122 U24.1 U27.8 U27.11 U27.14 U27.20 U27.21 U27.32 U28.8 | length 11474.1
  Top Layer w6: R140.2@3585,6083.5 3616.5,6083.5 3625,6075 3690,6075
  Top Layer w8: R140.2@3585,6083.5 3543.5,6083.5 3505,6045 3505,5965 v7(3525,5945) C168.2@3648.5,5945 ; 3690,6075 3721.5,6043.5 R139.2@3730,6043.5 3730,6005 v2(3750,5985) ; C167.2@3860,6106.5 v2(3860,6155) ; C165.2@3890,5525 3900,5535 v2(3935,5535) ; R142.1@4046.5,5525 4085,5525 v2(4100,5540) ; v4(4250,5985) C166.2@4323.5,5985 C166.2@4325,5985 ; v2(4495,6305) 4535,6305 4590,6360 R120.2@4625,6360 ; v2(5095,6370) 5135,6330 R121.2@5135,6296.5
  Top Layer w10: v2(4340,6680) 4353.5,6693.5 C180.1@4375,6693.5 C180.1@4375,6690 ; U24.1@4449.41,6691.61 4376.61,6691.61 C180.1@4375,6690 ; R122.2@4545,7020 4520,7020 4505,7005 4505,6925 4620,6810 DVDD_3V3.1@4620,6695 ; R120.2@4625,6360 4628.5,6360 C141.1@4690,6298.5 ; DVDD_3V3.1@4625,6695 4625,6665 4558.43,6598.43 4421.57,6598.43 4375,6645 C180.1@4375,6690 ; C141.1@4690,6300 4695.16,6294.84 U21.29@4695.16,6227.05 4695.16,6094.84 v2(4720,6070) ; U21.16@4773.9,5982.95 4757.05,5982.95 4755,5985 4755,5945 4775,5925 C139.1@4775,5911.5 4838.5,5911.5 C140.1@4840,5910 ; C140.1@4840,5911.5 4871.5,5911.5 v2(4900,5940)
  Signal Layer 1 w8: v2(3935,5535) 4095,5535 v2(4100,5540)
  Signal Layer 2 w8: v2(3750,5985) 3780,5955 3930,5955 3940,5965 4065,5965 v2(4080,5950) ; v2(4235,6445) 4230,6445 4215,6430 v2(4215,6360) 4250,6360 4276.87,6333.13 4276.87,6303.13 v2(4280,6300) 4300,6280 4475,6280 4495,6300 v2(4495,6305) ; v2(4450,5800) 4795,5800 4900,5905 v2(4900,5940) ; v2(4720,6070) 4720,6080 5010,6370 v2(5095,6370)
  Signal Layer 3 w10: v2(3750,5985) 3753.87,5988.87 3753.87,6178.87 3890,6315 3980,6315 v2(4260,6595) ; v2(4720,6070) 4795,6070 4900,5965 v2(4900,5940)
  Signal Layer 5 w8: v2(3750,5985) 3820,6055 4080,6055 v2(4100,6075)
  Signal Layer 5 w10: v2(4260,6595) 4260,6600 v2(4340,6680)
  Bottom Layer w6: 3540,5885 3548.62,5876.38 U23.47@3581.85,5876.38 3618.62,5876.38 3630,5865 3630,5855 ; U23.39@3581.85,5750.39 3620.39,5750.39 ; 3630,5760 3620.39,5750.39 ; 3635,5750 3634.61,5750.39 3620.39,5750.39 ; U23.28@3703.9,5596.85 3703.9,5556.1 3715,5545 ; 3705,6145 3703.9,6146.1 U23.69@3703.9,6203.15 3703.9,6243.9 3705,6245 ; 3730,5670 3735.39,5664.61 U23.26@3735.39,5596.85 3735.39,5545.39 3735,5545 ; v2(3860,6155) 3861.38,6156.38 U23.79@3861.38,6203.15 ; 3890,5535 3892.87,5537.87 U23.16@3892.87,5596.85 ; U23.8@4018.86,5596.85 4033.15,5596.85 U23.7@4034.61,5595.39 ; U23.90@4034.61,6203.15 4034.61,6171.33 4041.87,6164.06 4041.87,6118.13 ; 4040,5545 4034.61,5550.39 U23.7@4034.61,5595.39 ; v2(4080,5950) 4080,5940 4127.87,5892.13 U23.113@4188.15,5892.13 ; v2(4100,6075) 4106.87,6068.13 4139.06,6068.13 4152.04,6081.1 U23.101@4188.15,6081.1 ; U23.122@4188.15,5750.39 4085.39,5750.39 4035,5700 4035,5595 U23.7@4034.61,5595.39
  Bottom Layer w8: 3540,5885 3525,5900 v7(3525,5945) 3528.15,5941.85 3581.85,5941.85 3581.85,5950 ; R99.1@3596.36,7036.36 3595,7035 R99.1@3596.5,7035 C128.1@3663.5,7035 ; 3630,5760 3630,5855 ; 3635,5750 3650,5750 3730,5670 ; J17.5@3663.5,6958.5 C128.1@3663.5,7035 ; C128.1@3663.5,7040 C128.1@3663.5,7035 ; J17.5@3665,6955 3670,6955 3715,7000 3805,7000 3814.47,6990.53 3815,6990 ; R146.1@3690,6361.5 R146.1@3693.5,6361.5 ; R146.1@3690,6365 R146.1@3693.5,6361.5 ; 3703.9,6143.9 3698.13,6138.13 3698.13,6101.87 3730,6070 3730,6005 v2(3750,5985) 3860,6095 v2(3860,6155) ; 3705,6245 3710,6250 3750,6250 3762.87,6262.87 3762.87,6317.87 3720.75,6360 3720,6360 3718.5,6361.5 R146.1@3693.5,6361.5 ; 3715,5545 3735,5545 3855,5545 3865,5535 3890,5535 v2(3935,5535) ; 4040,5545 4095,5545 v2(4100,5540) ; 4041.87,6116.87 4045,6113.75 4045,6095 4065,6075 v2(4100,6075) ; v2(4215,6360) 4225.47,6370.47 U27.11@4286.69,6370.47 ; v2(4235,6445) 4230,6445 4245.47,6429.53 U27.14@4286.69,6429.53 ; v4(4250,5985) R151.2@4310,5985 ; v2(4280,6300) 4286.69,6306.69 U27.8@4311.1,6306.69 ; R151.2@4305,5980 R151.2@4310,5985 ; R151.2@4320,5986.5 4311.5,5986.5 R151.2@4310,5985 ; R151.2@4325,5985 R151.2@4310,5985 ; R151.2@4326.5,5986.5 R152.2@4385,5986.5 ; R152.2@4385,5985 4420,5985 4430,5975 4430,5850 4450,5830 v2(4450,5800) 4447.8,5802.2 U28.8@4418.39,5802.2 ; U27.32@4473.31,6331.1 4499.41,6305 v2(4495,6305)
  Bottom Layer w10: 3814.47,6990.53 3815,6770 ; 3815,6990 3815,6770 ; v2(4235,6445) 4235,6530 4278.5,6573.5 4281.5,6573.5 ; C176.2@4310,6573.5 4281.5,6573.5 ; C176.2@4311.5,6573.5 C175.1@4373.5,6573.5 ; U27.20@4370,6495 U27.20@4370.16,6494.84 ; C175.1@4375,6573.5 C175.1@4373.5,6573.5 ; U27.21@4389.84,6493.31 4371.69,6493.31 U27.20@4370.16,6494.84 ; v2(5095,6370) 5211.5,6486.5 R123.2@5211.5,6800 ; 3815,6770 3960,6625 4230,6625 v2(4260,6595) 4281.5,6573.5 ; U27.20@4370.16,6494.84 4370.16,6570.16 C175.1@4373.5,6573.5
EN: J7.2 U1.39 U10.2 U11.2 | length 8029.2
  Signal Layer 2 w10: v2(2185,5475) 2185,5285 2330,5140 3090,5140 3380,5140 3475,5235 4825,5235 4940.35,5350.35 5079.65,5350.35 J7.2@5125,5305 ; v2(2915,4110) 3000,4025 v4(3855,4025)
  Signal Layer 3 w10: v2(2185,5475) v4(2185,6035) 2185,6840 v4(2240,6895) ; v4(3855,4025) 3855,4070 4650,4865 5025,4865 5065,4905 ; 5065,4915 5065,4905 ; J7.2@5125,5305 5120,5305 5065,5250 5065,4905
  Bottom Layer w8: v2(2915,4110) 2962.55,4110 3031.1,4041.45 U1.39@3031.1,3998.46
  Bottom Layer w10: U11.2@2150,6045 2175,6045 v4(2185,6035) ; U10.2@2190,6895 v4(2240,6895)
EN2: J8.2 U1.43 | length 3201.7
  Signal Layer 2 w10: v2(3060,4120) 3060,4240 3120,4300 3740,4300 3987.13,4547.13 3987.13,4677.87 4025,4715.75 4025,4825 4115,4915 4970,4915 5005,4950 v4(5185,4950)
  Signal Layer 3 w10: v4(5185,4950) 5185,5245 J8.2@5245,5305
  Bottom Layer w8: v2(3060,4120) 3060,4107.45 3109.84,4057.61 U1.43@3109.84,3998.46
EN3: J25.2 U6.39 | length 1809.4
  Signal Layer 2 w10: v4(4915,4110) 4962.5,4062.5 5062.5,4062.5 5135,4135 6005,4135 ; 6010,4140 6005,4135 ; v2(6055,4185) 6005,4135
  Signal Layer 3 w10: v2(6055,4185) 6055,4520 J25.2@6110,4575
  Bottom Layer w9.8: v4(4915,4110) 4955,4110 5026.66,4038.34 5026.66,4038.05 5031.1,4033.61 U6.39@5031.1,4002.4
EN4: J26.2 U6.43 | length 1651.1
  Signal Layer 2 w10: v4(5060,4120) 5060,4175 5165,4280 6140,4280 6175,4315 v2(6175,4320)
  Signal Layer 3 w10: v2(6175,4320) 6175,4515 J26.2@6235,4575
  Bottom Layer w9.8: v4(5060,4120) 5095,4085 5095,4069.99 5097.35,4067.64 5097.35,4067.33 5109.84,4054.84 U6.43@5109.84,4002.4
FB: C13.1 C121.2 C196.1 CC.1 D3.2 D5.1 J2.11 J28.11 R44.2 R160.2 R161.2 R163.2 R168.2 U1.45 U6.45 | length 11651.6
  Top Layer w10: v2(2305,5895) R163.2@2305,5955 ; D3.2@3128.35,5785 3128.35,5761.65 3140,5750 3195,5750 3205,5740 D5.1@3205,5700 ; D5.1@3203.31,5705 3203.31,5671.69 3220,5655 ; v2(3220,5625) 3220,5655 ; C121.2@3290,5655 3220,5655 ; C121.2@3290,5656.5 3368.5,5656.5 CC.1@3400,5625 CC.1@3405,5620
  Signal Layer 2 w10: v2(2305,5895) 2305,5690 2370,5625 v2(3220,5625) 3430,5625 3550,5505 4205,5505 4250,5460 4250,5370 J2.11@4300,5320 ; v2(2495,4420) 2595,4420 2625,4390 2715,4390 2745,4420 3310,4420 v2(3330,4400) 3405,4325 v2(3620,4325) ; v2(4495,4420) 5310,4420 5330,4400 5350,4420 v4(5640,4420)
  Signal Layer 3 w9.8: v2(3140,4085) 3140,4160 3235,4255 v2(3285,4255) ; v4(5140,4085) 5140,4160 5235,4255 v2(5285,4255)
  Bottom Layer w9.8: C13.1@3135,4125 3140,4120 v2(3140,4085) 3140,4080 3149.21,4070.79 U1.45@3149.21,4002.4 ; v2(3285,4255) 3620,4255 ; J2.11@4300,5320 4340,5280 4340,5030 ; v2(5285,4255) 5330,4300 v2(5330,4405) 5330,4650 J28.11@5290,4690
  Bottom Layer w10: v2(2495,4420) 2485,4420 2455,4390 2455,3915 2540,3830 R161.2@2540,3786.5 R161.2@2540,3785 ; v2@3620,4320 3620,4255 3620,3810 3700,3730 R160.2@3700,3726.5 ; v2(3620,4325) 3635,4325 3730,4420 ; 4340,5030 3730,4420 ; v2@4500,4420 v2(4495,4420) v2@4485,4420 ; R44.2@4540,3786.5 4540,3830 4455,3915 4455,4390 v2@4485,4420 ; C196.1@5135,4130 C196.1@5135,4127.44 5135,4086.57 5134.21,4085.79 5149.21,4070.79 U6.45@5149.21,4002.4 ; v4@5640,4425 v4(5640,4420) 5699.93,4360.07 R168.2@5699.93,3726.5 ; 3730,4420 v2@4485,4420
HO1: R26.1 R30.1 U1.22 | length 2680.8
  Top Layer w24: v1(1890,2335) R30.1@1980,2335 ; v1@1895,1830 R26.1@1960,1830
  Signal Layer 2 w24: v1(1890,1830) v1(1890,2335) 1890,2795 2665,3570 v4(3010,3570)
  Bottom Layer w9.8: 3031.1,3614.07 U1.22@3031.1,3681.54
  Bottom Layer w16: v4(3010,3570) 3010,3585 3030,3605 3030,3614.07
HO2: R37.1 R41.1 U1.15 | length 4193.5
  Top Layer w24: v1(6310,2840) 6350,2800 R41.1@6350,2785 ; v1(6350,2355) 6350,2290 R37.1@6355,2285
  Signal Layer 2 w24: v4(3190,3580) 4170.08,3580 4538.2,3211.87 4538.2,3211.8 4910,2840 v1(6310,2840) 6355,2795 6355,2360 v1(6350,2355)
  Bottom Layer w9.8: 3168.9,3610 U1.15@3168.9,3681.54
  Bottom Layer w16: 3167.82,3616.25 3167.82,3611.08 3168.9,3610 3170,3610 3190,3590 v4(3190,3580)
HO3: R179.1 R183.1 U6.22 | length 4428.3
  Signal Layer 2 w24: v1(1845,2335) v1(1845,2835) 1884.92,2835 2654.92,3605 2990,3605 3028.13,3643.13 3028.13,3643.2 3046.8,3661.87 3046.87,3661.87 3050,3665 3270,3665 3305,3630 3605,3630 3630,3655 4255,3655 4440,3470 4935,3470 4970,3505 4970,3545 4995,3570 v4(5010,3570)
  Bottom Layer w9.8: U6.22@5031.1,3677.6 5031.1,3638.29 5033.28,3636.11 5033.28,3613.28
  Bottom Layer w16: v4(5010,3570) 5010,3590 5033.28,3613.28
  Bottom Layer w24: R179.1@1845,2265 v1(1845,2335) ; R183.1@1845,2770 v1(1845,2835)
HO4: R190.1 R194.1 U6.15 | length 3135.3
  Signal Layer 2 w24: v4(5175,3550) 6330,3550 6415,3465 v1(6415,2285) v1(6415,1850)
  Bottom Layer w9.8: 5168.9,3601.1 U6.15@5168.9,3677.6
  Bottom Layer w16: 5168.9,3601.1 5168.9,3556.1 v4(5175,3550)
  Bottom Layer w24: R194.1@6355,2285 v1(6415,2285) ; R190.1@6360,1850 v1(6415,1850)
I2C_SCL: R152.1 U23.112 U28.6 | length 353.1
  Bottom Layer w6: U23.112@4188.15,5907.87 4247.13,5907.87 4263.06,5891.94
  Bottom Layer w8: 4263.06,5891.94 4263.13,5891.87 4310.47,5891.87 ; 4310.4,5891.94 4310.47,5891.87 ; 4343.62,5891.94 4324.6,5891.94 4324.53,5891.87 4310.47,5891.87 ; 4345.47,5891.87 4356.87,5891.87 R152.1@4385,5920 ; U28.6@4367.2,5802.2 4367.2,5877.2 ; 4375,5885 4367.2,5877.2 ; R152.1@4385,5923.5 R152.1@4385,5920 ; 4367.2,5877.2 4385,5895 R152.1@4385,5920
I2C_SDA: R151.1 U23.111 U28.5 | length 333.1
  Signal Layer 3 w8: v2(4275,5950) 4335,5890 v2(4335,5865)
  Bottom Layer w6: U23.111@4188.15,5923.62 4218.62,5923.62 4245,5950 v2(4275,5950)
  Bottom Layer w8: v2(4275,5950) 4301.5,5923.5 R151.1@4320,5923.5 ; R151.1@4319.25,5924.25 R151.1@4320,5925 ; v2(4335,5865) 4340,5865 4341.61,5863.39 U28.5@4341.61,5802.2
I_TOTAL: R16.3 R21.2 R32.1 R173.2 R184.1
  other v2: 3600,2180 3650,2180 3700,2180 3750,2180 3800,2180 3850,2180 3900,2180 3950,2180 4050,2180 4100,2180 4150,2180 4200,2180 4300,2180 4425,2180 4475,2180 4525,2180 3600,2230 3650,2230 3700,2230 3750,2230 3800,2230 3850,2230 3900,2230 3950,2230 4050,2230 4100,2230 4150,2230 4200,2230 4300,2230 4425,2230 4475,2230 4525,2230 3600,2280 3650,2280 3700,2280 3750,2280 3800,2280 3850,2280 3900,2280 3950,2280 4050,2280 4100,2280 4150,2280 4200,2280 4250,2280 4300,2280 4425,2280 4475,2280 4525,2280 3600,2330 3650,2330 3700,2330 3750,2330 3800,2330 3850,2330 3900,2330 3950,2330 4050,2330 4100,2330 4150,2330 4200,2330 4250,2330 4300,2330 4425,2330 4475,2330 4525,2330 3600,2380 3650,2380 3700,2380 3750,2380 3800,2380 3850,2380 3900,2380 3950,2380 4050,2380 4100,2380 4150,2380 4200,2380 4250,2380 4300,2380 4425,2380 4475,2380 4525,2380 3600,2430 3650,2430 3700,2430 3750,2430 3800,2430 3850,2430 3900,2430 3950,2430 4050,2430 4100,2430 4150,2430 4200,2430 4250,2430 4300,2430 4425,2430 4475,2430 4525,2430 3600,2480 3650,2480 3700,2480 3750,2480 3800,2480 3850,2480 3900,2480 3950,2480 4050,2480 4100,2480 4150,2480 4200,2480 4250,2480 4300,2480 4425,2480 4475,2480 4525,2480 3600,2530 3650,2530 3700,2530 3750,2530 3800,2530 3850,2530 3900,2530 3950,2530 4050,2530 4100,2530 4150,2530 4200,2530 4250,2530 4300,2530 4425,2530 4475,2530 4525,2530 3600,2580 3650,2580 3700,2580 3750,2580 3800,2580 3850,2580 3900,2580 3950,2580 4050,2580 4100,2580 4150,2580 4200,2580 4250,2580 4300,2580 4425,2580 4475,2580 4525,2580 3600,2630 3650,2630 3700,2630 3750,2630 3800,2630 3850,2630 3900,2630 3950,2630 4050,2630 4100,2630 4150,2630 4200,2630 4250,2630 4300,2630 3600,2680 3650,2680 3700,2680 3750,2680 3800,2680 3850,2680 3900,2680 3950,2680 4050,2680 4100,2680 4150,2680 4200,2680 4250,2680 4300,2680 4425,2680 4475,2680 4525,2680 3600,2730 3650,2730 3700,2730 3750,2730 3800,2730 3850,2730 3900,2730 3950,2730 4050,2730 4100,2730 4150,2730 4200,2730 4250,2730 4300,2730 4425,2730 4475,2730 4525,2730 3600,2780 3650,2780 3700,2780 3750,2780 3800,2780 3850,2780 3900,2780 3950,2780 4050,2780 4100,2780 4150,2780 4200,2780 4250,2780 4300,2780 4425,2780 4475,2780 4525,2780
  other v9: 4425,2630 4475,2630 4525,2630
IBAT: C113.2 R73.1 R114.1 | length 1111.1
  Top Layer w12: C113.2@2840,6200 2836.5,6203.5 R73.1@2836.5,6290 v7(2890,6290) ; v4(3735,6275) 3747.01,6275 3748.5,6273.5 R114.1@3795,6273.5
  Signal Layer 2 w12: v7(2890,6290) 2960,6220 3695,6220 3735,6260 v4(3735,6275)
IBAT_P: C110.1 R71.1 R74.1 U14.3 | length 801.1
  Top Layer w12: C110.1@2755,5800 2751.5,5796.5 R71.1@2680,5796.5 U14.3@2680,5926.65 2680,5995 2720,6035 2860,6035 2890,6065 2890,6240 2935,6285 R74.1@2983.5,6285
IOUT1: C2.2 J2.5 R3.1 U1.37 | length 2459.9
  Signal Layer 3 w8: v7(2850,4290) 2850,4455 2935,4540 3165,4540 3245,4460 3310,4460 3860,5010 3860,5090 4000,5230 J2.5@4000,5320
  Bottom Layer w8: C2.2@2710,4315 2830,4315 2850,4295 v7(2850,4290) 2850,4080 2870,4060 2967.65,4060 2991.73,4035.92 U1.37@2991.73,3998.46
  Bottom Layer w9.8: R3.1@2650,4312.56 C2.2@2710,4312.56
IOUT2: C17.1 J2.9 R20.2 U1.38 | length 2350
  Signal Layer 3 w10: v2(2890,4085) 2890,4305 2980,4395 v7(3015,4395)
  Bottom Layer w8: v2(2890,4085) 2965.1,4085 3011.42,4038.68 U1.38@3011.42,3998.46
  Bottom Layer w10: v7(3015,4395) 3094.92,4315.08 C17.1@3192.48,4315.08 ; C17.1@3190,4317.55 C17.1@3192.48,4315.08 ; 4200,5045 4200,5040 ; J2.9@4200,5300 4200,5040 ; C17.1@3192.48,4315.08 R20.2@3240,4315.08 3475.08,4315.08 4200,5040
IOUT3: C9.2 J28.5 R9.1 U6.37 | length 1059.4
  Signal Layer 3 w8: v4(4850,4290) 4850,4460 4990,4600 J28.5@4990,4690
  Bottom Layer w9.8: v4(4850,4290) 4850,4080 4885,4045 4965,4045 4991.73,4018.27 U6.37@4991.73,4002.4
  Bottom Layer w10: R9.1@4650,4310 4830,4310 v4(4850,4290)
IOUT4: C205.1 J28.9 R171.2 U6.38 | length 1187.3
  Signal Layer 3 w10: v4(4890,4085) 4890,4305 4980,4395 v4(5015,4395)
  Bottom Layer w9.8: v4(4890,4085) 4955.01,4085 5008.98,4031.02 5008.98,4030.73 5011.42,4028.3 U6.38@5011.42,4002.4
  Bottom Layer w10: v4(5015,4395) 5094.92,4315.08 C205.1@5192.48,4315.08 ; J28.9@5190,4690 5192.48,4687.52 C205.1@5192.48,4315.08 ; R171.2@5240,4315 5239.92,4315.08 C205.1@5192.48,4315.08
IREF: J18.2 J18.4 R93.1 | length 1447.5
  Top Layer w10: R93.1@3270,6315 3295,6290 v4(3310,6290)
  Signal Layer 5 w10: J18.4@2550,6900 2600,6950 2685,6950 2700,6935 2700,6520 2730,6490 3110,6490 v4(3310,6290)
  Bottom Layer w10: J18.2@2450,6900 J18.4@2550,6900
ISEN+: R31.1 R63.1 R195.2 | length 1283.5
  Top Layer w10: R63.1@2540,4315 2455,4400 2455,4510 2685,4740 2750,4740 2935,4925 2935,5040 2909.87,5065.13 2909.87,5065.3 2895.3,5079.87 2895.13,5079.87 2890,5085 2880,5085 2855,5110 ; R31.1@2542.44,4262.44 R63.1@2542.44,4310 ; 2855,5120 2855,5110 ; R195.2@2898.5,5195 2870,5195 2855,5180 2855,5110
ISEN-: R42.1 R64.1 R65.2 | length 1496.7
  Top Layer w10: R42.1@2542.44,4485 2542.44,4532.16 2714.53,4704.25 2799.25,4704.25 3035,4940 3435,4940 3550,5055 R64.1@3550,5170 ; R65.2@3456.5,5210 3510,5210 3515,5210 R64.1@3550,5175 ; R64.1@3552.44,5175 R64.1@3552.44,5177.44
JTAG_RESET: J22.1 R141.1 S2.2 | length 3390.1
  Top Layer w8: v2(3390,6350) 3400,6360 S2.2@3475,6360 ; v2(3795,5980) R141.1@3795,6043.5
  Signal Layer 5 w8: v2(3795,5980) 3770,5955 3625,5955 3600,5980 3600,6000 3390,6210 v2(3390,6350) 3390,6390 3785,6785 5369.39,6785 5428.74,6844.35 5499.35,6844.35 J22.1@5660,7005
LDACn: J17.7 R99.2 U17.1 | length 732.1
  Top Layer w8: U17.1@3174.06,6619.13 3254.92,6700 v7(3485,6700)
  Bottom Layer w8: v7(3485,6700) 3515,6730 3515,6905 J17.7@3565,6955 3530,6990 R99.2@3530,7040
LO1: R27.1 R28.1 U1.20 | length 3509.4
  Top Layer w24: R27.1@2090,1525 R27.1@2090,1530 v1(2090,1595) ; v1(2480,1600) 2525,1600 R28.1@2595,1530 R28.1@2595,1525
  Signal Layer 2 w24: v1(2090,1595) 2095,1600 v1(2480,1600) 2555,1675 2569.92,1675 2571.8,1676.87 3151.87,1676.87 3330,1855 3330,2805 3085,3050 3085,3574.92 3078.13,3581.8 3078.13,3581.87 3060,3600 v4(3060,3630)
  Bottom Layer w9.8: 3070.47,3640.47 U1.20@3070.47,3681.54
  Bottom Layer w12: v4(3060,3630) 3070.47,3640.47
